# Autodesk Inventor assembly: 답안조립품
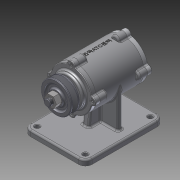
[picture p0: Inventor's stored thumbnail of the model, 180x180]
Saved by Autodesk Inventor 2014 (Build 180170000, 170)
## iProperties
Created: 2015-12
Part Number: 답안조립품
Document SubType Name: Assembly
Designer: basic
Author: basic
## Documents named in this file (11)
- C:\Users\basic\Desktop\451208V1030\답안조립품.iam
- C:\Users\basic\Desktop\451208V1030\V-벨트풀리.ipt
- C:\Users\basic\Desktop\451208V1030\너트 M12x1.25.ipt
- C:\Users\basic\Desktop\451208V1030\베어링 6204.ipt
- C:\Users\basic\Desktop\451208V1030\본체.ipt
- C:\Users\basic\Desktop\451208V1030\볼트 M4 x 12.ipt
- C:\Users\basic\Desktop\451208V1030\오일실.ipt
- C:\Users\basic\Desktop\451208V1030\축.ipt
- C:\Users\basic\Desktop\451208V1030\커버.ipt
- C:\Users\basic\Desktop\451208V1030\커버2.ipt
- C:\Users\basic\Desktop\451208V1030\키(4 x 4 x 12).ipt
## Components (6 placed, 5 different names)
1. V-벨트풀리:2
2. KS B 2023 6204 - 20 x 47 x 14:2
3. KS B 2804 D D - 20 32 8:2
4. KS B 1311 (I) 4 x 4 x 12:2
5. KS B 2023 6204 - 20 x 47 x 14:3
6. KS B 1012 클래스 1 일반 - 미터 M12x1.25:1 — 각도:1
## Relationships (1: Angle 1)
- 각도:1 [Angle]: KS B 1012 클래스 1 일반 - 미터 M12x1.25:1
